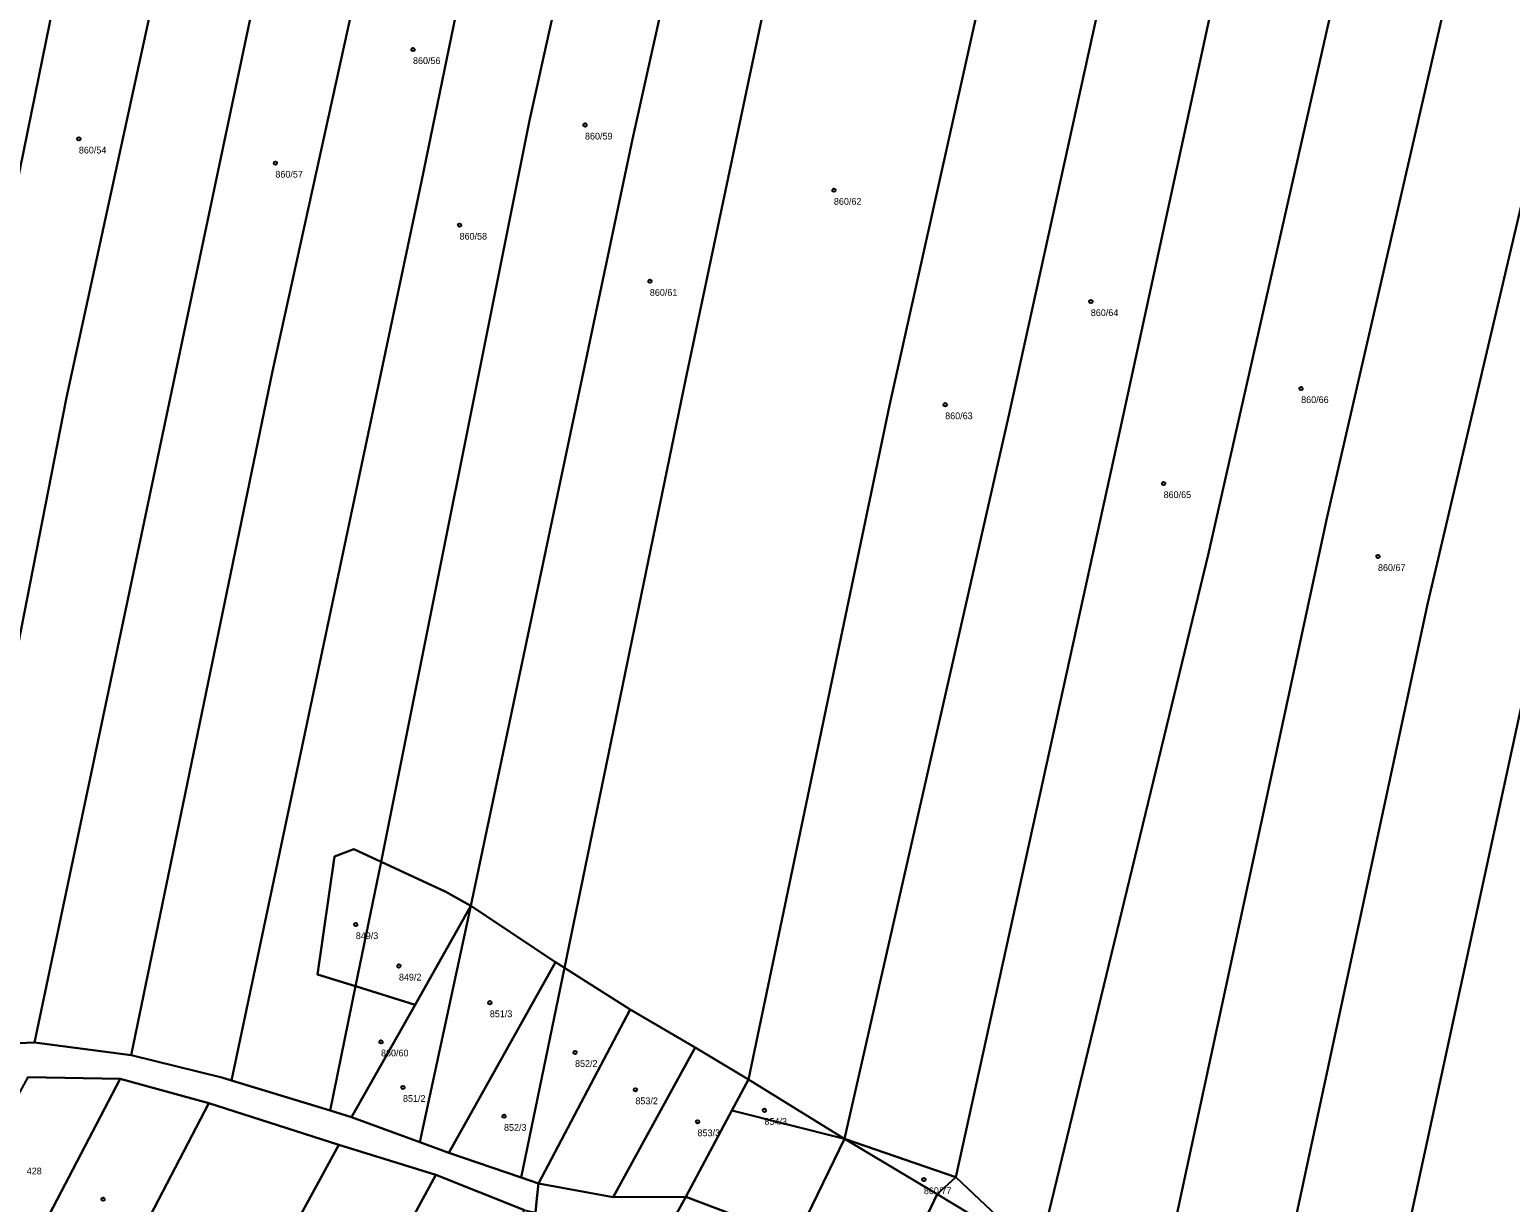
# Model space of a CAD drawing. Extents: x -587171 to -555306, y -1167727 to -1074732.
# Drawn here: x -585270.7 to -585050.4, y -1165522.6 to -1165348.1 of the extents above; entities that cross this region are included whole.
import ezdxf

# ---------------------------------------------------------------- set-up
doc = ezdxf.new("R2010")
doc.units = 0
doc.layers.add('Definiční body', color=7, linetype='Continuous')
doc.layers.add('Polygon parcely', color=7, linetype='Continuous')

msp = doc.modelspace()

# ---------------------------------------------------------------- linework, layer by layer
at = {"layer": 'Definiční body'}
for centre in [(-585213.62, -1165351.06), (-585188.03, -1165362.29), (-585263.33, -1165364.37), (-585234.09, -1165367.96), (-585151, -1165372.01), (-585206.69, -1165377.19), (-585178.38, -1165385.55), (-585112.78, -1165388.56), (-585081.49, -1165401.51), (-585134.45, -1165403.91), (-585101.95, -1165415.65), (-585070.06, -1165426.49), (-585222.13, -1165481.28), (-585215.71, -1165487.44), (-585202.19, -1165492.9), (-585218.38, -1165498.73), (-585189.51, -1165500.3), (-585215.11, -1165505.5), (-585180.53, -1165505.85), (-585200.08, -1165509.81), (-585161.33, -1165508.92), (-585171.29, -1165510.61), (-585137.62, -1165519.23), (-585259.73, -1165522.15)]:
    msp.add_circle(centre, 0.25, dxfattribs=at)
at = {"layer": 'Polygon parcely'}
for points in [[(-585269.99, -1165304.56), (-585295.53, -1165420.05), (-585283.24, -1165423.26), (-585264.87, -1165333.37), (-585245.61, -1165246.39), (-585257.13, -1165241.31), (-585261.15, -1165263.91), (-585261.82, -1165277.56), (-585264.69, -1165292.05)], [(-585284.13, -1165499.44), (-585265.18, -1165402.83), (-585232.38, -1165252.13), (-585245.61, -1165246.39), (-585264.87, -1165333.37), (-585283.24, -1165423.26), (-585286.31, -1165438.54), (-585292.4, -1165465.31), (-585293.41, -1165470.16), (-585299.66, -1165500.12)], [(-585242.98, -1165370.97), (-585219.13, -1165257.86), (-585232.38, -1165252.13), (-585265.18, -1165402.83), (-585284.13, -1165499.44), (-585269.94, -1165498.81)], [(-585204.86, -1165264.14), (-585219.13, -1165257.86), (-585242.98, -1165370.97), (-585269.94, -1165498.81), (-585255.53, -1165500.73), (-585234.5, -1165398.92)], [(-585212.37, -1165370.69), (-585191.64, -1165269.99), (-585204.86, -1165264.14), (-585234.5, -1165398.92), (-585255.53, -1165500.73), (-585242.08, -1165504.02), (-585240.64, -1165504.46)], [(-585177.35, -1165276.15), (-585191.64, -1165269.99), (-585212.37, -1165370.69), (-585240.64, -1165504.46), (-585225.94, -1165508.95), (-585222.15, -1165490.46), (-585227.84, -1165488.69), (-585225.28, -1165471.14), (-585222.42, -1165470.08), (-585218.35, -1165471.96), (-585196.3, -1165361.63)], [(-585162.75, -1165282.51), (-585164.51, -1165281.61), (-585177.35, -1165276.15), (-585196.3, -1165361.63), (-585218.35, -1165471.96), (-585208.71, -1165476.4), (-585205.91, -1165477.98), (-585205.01, -1165478.49), (-585180.96, -1165364.39)], [(-585173.1, -1165400.25), (-585149.45, -1165288.27), (-585162.75, -1165282.51), (-585180.96, -1165364.39), (-585205.01, -1165478.49), (-585192.42, -1165486.86), (-585191.09, -1165487.7)], [(-585142.72, -1165404.05), (-585119.83, -1165301.09), (-585149.45, -1165288.27), (-585173.1, -1165400.25), (-585191.09, -1165487.7), (-585181.3, -1165493.9), (-585171.65, -1165499.59), (-585163.7, -1165504.31)], [(-585125.01, -1165405.72), (-585103.58, -1165308.33), (-585119.83, -1165301.09), (-585142.72, -1165404.05), (-585163.7, -1165504.31), (-585149.42, -1165513.18)], [(-585088.26, -1165314.75), (-585103.58, -1165308.33), (-585125.01, -1165405.72), (-585149.42, -1165513.18), (-585132.85, -1165518.86), (-585108.41, -1165407.62)], [(-585095.33, -1165426.27), (-585071.65, -1165321.64), (-585078.73, -1165318.74), (-585085.42, -1165315.98), (-585088.26, -1165314.75), (-585108.41, -1165407.62), (-585132.85, -1165518.86), (-585120.57, -1165530.49)], [(-585077.64, -1165420.59), (-585056.47, -1165328.63), (-585062.87, -1165325.77), (-585069.26, -1165322.62), (-585071.65, -1165321.64), (-585095.33, -1165426.27), (-585120.57, -1165530.49), (-585103.04, -1165538.72)], [(-585062.62, -1165433.4), (-585039.8, -1165336.06), (-585056.47, -1165328.63), (-585077.64, -1165420.59), (-585103.04, -1165538.72), (-585086.66, -1165545.21)], [(-585045.59, -1165434.24), (-585024.23, -1165343.01), (-585039.8, -1165336.06), (-585062.62, -1165433.4), (-585086.66, -1165545.21), (-585070.55, -1165549.52)], [(-585028.83, -1165437.23), (-585008.06, -1165350.23), (-585024.23, -1165343.01), (-585045.59, -1165434.24), (-585070.55, -1165549.52), (-585059.09, -1165552.7), (-585056.3, -1165550.68), (-585052.65, -1165547.24)], [(-585225.28, -1165471.14), (-585227.84, -1165488.69), (-585222.15, -1165490.46), (-585218.35, -1165471.96), (-585222.42, -1165470.08)], [(-585222.15, -1165490.46), (-585213.32, -1165493.2), (-585205.01, -1165478.49), (-585205.91, -1165477.98), (-585208.71, -1165476.4), (-585218.35, -1165471.96)], [(-585205.01, -1165478.49), (-585213.32, -1165493.2), (-585222.76, -1165509.92), (-585212.6, -1165513.65)], [(-585192.42, -1165486.86), (-585205.01, -1165478.49), (-585212.6, -1165513.65), (-585208.3, -1165515.23)], [(-585191.09, -1165487.7), (-585192.42, -1165486.86), (-585208.3, -1165515.23), (-585197.51, -1165518.93)], [(-585181.3, -1165493.9), (-585191.09, -1165487.7), (-585197.51, -1165518.93), (-585194.97, -1165519.8)], [(-585213.32, -1165493.2), (-585222.15, -1165490.46), (-585225.94, -1165508.95), (-585222.76, -1165509.92)], [(-585181.3, -1165493.9), (-585194.97, -1165519.8), (-585183.82, -1165521.83), (-585171.65, -1165499.59)], [(-585163.7, -1165504.31), (-585171.65, -1165499.59), (-585183.82, -1165521.83), (-585173.05, -1165521.81), (-585166.17, -1165508.94)], [(-585269.46, -1165527.81), (-585257.18, -1165504.24), (-585270.91, -1165503.96), (-585280.04, -1165520.6), (-585276.92, -1165522.22), (-585277.49, -1165523.33)], [(-585257.72, -1165534.25), (-585243.97, -1165507.84), (-585257.18, -1165504.24), (-585269.46, -1165527.81), (-585260.46, -1165532.75)], [(-585149.42, -1165513.18), (-585163.7, -1165504.31), (-585166.17, -1165508.94)], [(-585253.79, -1165567.57), (-585251.48, -1165563.33), (-585224.66, -1165514.03), (-585243.97, -1165507.84), (-585257.72, -1165534.25), (-585268.56, -1165555.08), (-585270.39, -1165558.55)], [(-585166.17, -1165508.94), (-585173.05, -1165521.81), (-585156.61, -1165528.01), (-585149.42, -1165513.18)], [(-585253.79, -1165567.57), (-585240.61, -1165574.73), (-585239.4, -1165572.46), (-585248.2, -1165567.73), (-585249.87, -1165566.83), (-585248.77, -1165564.79), (-585246.87, -1165561.25), (-585245.76, -1165559.22), (-585244.09, -1165560.13), (-585243.44, -1165558.91), (-585234.63, -1165563.6), (-585230.56, -1165556.07), (-585210.23, -1165518.54), (-585224.66, -1165514.03), (-585251.48, -1165563.33)], [(-585149.42, -1165513.18), (-585156.61, -1165528.01), (-585144.58, -1165540.29), (-585135.64, -1165521.4)], [(-585132.85, -1165518.86), (-585149.42, -1165513.18), (-585135.64, -1165521.4)], [(-585217.07, -1165561.01), (-585197.05, -1165523.79), (-585210.23, -1165518.54), (-585230.56, -1165556.07), (-585218.06, -1165563.01)], [(-585135.64, -1165521.4), (-585130.87, -1165524.27), (-585124.07, -1165528.38), (-585120.57, -1165530.49), (-585132.85, -1165518.86)], [(-585195.19, -1165522.02), (-585195.4, -1165524.11), (-585185.86, -1165525.98), (-585176.53, -1165528.23), (-585175.01, -1165525.42), (-585173.05, -1165521.81), (-585183.82, -1165521.83), (-585194.97, -1165519.8)], [(-585161.23, -1165535.74), (-585158.99, -1165531.99), (-585156.61, -1165528.01), (-585173.05, -1165521.81), (-585175.01, -1165525.42), (-585176.53, -1165528.23)], [(-585124.07, -1165528.38), (-585130.87, -1165524.27), (-585135.64, -1165521.4), (-585144.58, -1165540.29), (-585132.97, -1165553.39), (-585120.57, -1165530.49)]]:
    msp.add_lwpolyline(points, close=True, dxfattribs=at)
msp.add_lwpolyline([(-585270.91, -1165503.96), (-585257.18, -1165504.24), (-585243.97, -1165507.84), (-585224.66, -1165514.03), (-585210.23, -1165518.54), (-585197.05, -1165523.79), (-585195.4, -1165524.11), (-585195.19, -1165522.02), (-585194.97, -1165519.8), (-585197.51, -1165518.93), (-585208.3, -1165515.23), (-585212.6, -1165513.65), (-585222.76, -1165509.92), (-585225.94, -1165508.95), (-585240.64, -1165504.46), (-585242.08, -1165504.02), (-585255.53, -1165500.73), (-585269.94, -1165498.81), (-585284.13, -1165499.44)], dxfattribs=at)

# ---------------------------------------------------------------- texts
at = {"layer": 'Definiční body'}
for s, p in [('860/56', (-585213.62, -1165353.22)), ('860/59', (-585188.03, -1165364.45)), ('860/54', (-585263.33, -1165366.53)), ('860/57', (-585234.09, -1165370.12)), ('860/62', (-585151, -1165374.17)), ('860/58', (-585206.69, -1165379.35)), ('860/61', (-585178.38, -1165387.71)), ('860/64', (-585112.78, -1165390.72)), ('860/66', (-585081.49, -1165403.67)), ('860/63', (-585134.45, -1165406.07)), ('860/65', (-585101.95, -1165417.81)), ('860/67', (-585070.06, -1165428.65)), ('849/3', (-585222.13, -1165483.44)), ('849/2', (-585215.71, -1165489.6)), ('851/3', (-585202.19, -1165495.06)), ('860/60', (-585218.38, -1165500.89)), ('852/2', (-585189.51, -1165502.46)), ('851/2', (-585215.11, -1165507.66)), ('853/2', (-585180.53, -1165508.01)), ('854/3', (-585161.33, -1165511.08)), ('852/3', (-585200.08, -1165511.97)), ('853/3', (-585171.29, -1165512.77)), ('428', (-585271.08, -1165518.45)), ('860/77', (-585137.62, -1165521.39))]:
    msp.add_text(s, height=1, dxfattribs=at).set_placement(p)

doc.saveas('drawing.dxf')
